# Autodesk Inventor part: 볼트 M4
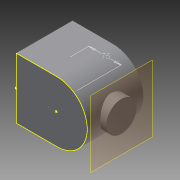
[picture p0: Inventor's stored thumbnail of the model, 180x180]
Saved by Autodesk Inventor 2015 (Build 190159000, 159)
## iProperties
Created: 2023-03
Part Number: 볼트 M4
Material: 일반
Document SubType Name: Modeling
Designer: 101548
Density: 1 g/cm^3
Appearance: 기본값
Author: 101548
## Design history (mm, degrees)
sketch "스케치1"
  geometry: 1 further point
sketch "스케치2"
  geometry: L1 (-65, -70)-(65, -70); L2 (65, -70)-(65, 70); L3 (65, 70)-(-65, 70); L4 (-65, 70)-(-65, -70); L5 (-65, -70)-(65, 70); L6 (65, -70)-(-65, 70); 1 further point
  constraints: 12 end point, 2 midpoint, 2 parallel, 1 horizontal, 1 perpendicular
  dimensions: "d0" = 130 distance of L3.end L2.end; "d1" = 140 distance of L2.end L1.end
extrude "돌출1" new body sketch "스케치2" distance "d2" = 94; taper "d3" = 0 deg
sketch "스케치3"
  geometry: L1 (94, 140)-(94, 0) reference; A1 r 70.001 centre (93.672, 70) between (94, 0) and (94, 140); 1 further point
  constraints: 2 point on circle, 1 centre point
extrude "돌출2" join sketch "스케치3" distance "d4" = 130; taper "d5" = 0 deg
sketch "스케치4"
  geometry: L1 (0, 140)-(0, 0) reference; L2 (0, 0)-(94, 0) reference; L3 (0, 140)-(94, 140) reference; A1 r 70.001 centre (93.672, 70) between (94, 0) and (94, 140) reference; 1 further point
node "작업 평면1"
sketch "스케치5"
  geometry: C1 r 35 at (0, 0); 1 further point
  constraints: 1 centre point, 1 coincident
  dimensions: "d7" = 70 diameter of C1
extrude "돌출3" join sketch "스케치5" stored distance "d8" = 130; taper "d9" = 0 deg
sketch "스케치6"
  geometry: L1 (0, 140)-(0, 0) reference; L2 (0, 0)-(94, 0) reference; L3 (0, 140)-(94, 140) reference; A1 r 70.001 centre (93.672, 70) between (94, 0) and (94, 140) reference; 1 further point
sketch "스케치7"
  geometry: L1 (163.673, 35)-(178, 35) reference; L2 (178, 35)-(178, -35) reference; L3 (178, -35)-(163.673, -35) reference; L4 (163.673, -35)-(163.673, -65) reference; L5 (163.673, -65)-(0, -65) reference; L6 (0, -65)-(0, 65) reference; L7 (0, 65)-(163.673, 65) reference; L8 (163.673, 65)-(163.673, 35) reference; L9 (0, -65)-(94, -65) reference; L10 (75, -59.274)-(75, -47); L11 (0, 65)-(94, 65) reference; L12 (75, -59.274)-(75, -47); L13 (75, -47)-(105, -47); L14 (105, -47)-(117.274, -59.274); L15 (117.274, -59.274)-(75, -59.274); 2 further points
  constraints: 10 end point, 3 perpendicular
  dimensions: "d10" = 75 distance from line of L6 point (75, 0); "d12" = 60 diameter of L13.end L10; "d13" = 135 deg angle of L13 L14
  node "절단 모서리 투영1"
feature "쉘1" dims "d14" = 5
revolve "회전1" stored, may be unused: angle "d15" = 90 deg
sketch "스케치8"
  geometry: L1 (0, 60)-(0, -60) reference; L2 (75, -65.271)-(75, 65); L3 (0, 65)-(94, 65) reference; 2 further points
  constraints: 2 end point, 1 point on line, 1 vertical
  dimensions: "d16" = 75 distance from line of L1 point (75, 0)
node "솔리드1"
other parameters: "d6" = 178
